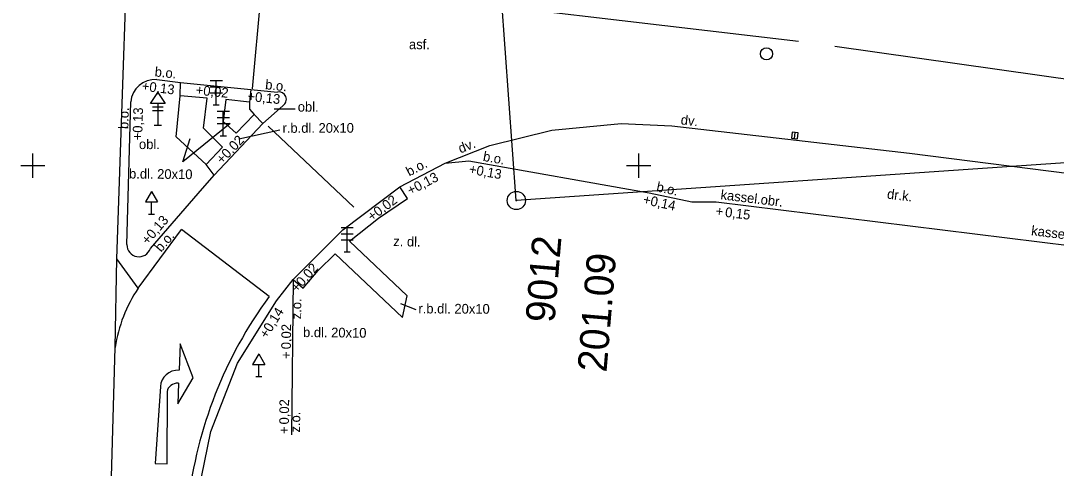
# Model space of a CAD drawing. Extents: x -598693 to -598240, y -1162454 to -1160800.
# Drawn here: x -598650.5 to -598607.77, y -1162412.48 to -1162394.03 of the extents above; entities that cross this region are included whole.
import ezdxf

# ---------------------------------------------------------------- set-up
doc = ezdxf.new("R2010")
doc.units = 0
for name, color, linetype in [('Vrstva 19', 7, 'Continuous'), ('Vrstva 2', 7, 'Continuous'), ('Vrstva 25', 7, 'Continuous'), ('Vrstva 44', 7, 'Continuous'), ('Vrstva 47', 7, 'Continuous'), ('Vrstva 49', 7, 'Continuous'), ('Vrstva 50', 7, 'Continuous'), ('Vrstva 61', 7, 'Continuous'), ('Vrstva 62', 7, 'Continuous'), ('Vrstva 7', 7, 'Continuous')]:
    doc.layers.add(name, color=color, linetype=linetype)

msp = doc.modelspace()

# ---------------------------------------------------------------- linework, layer by layer
at = {"layer": 'Vrstva 19'}
for p, q in [((-598642.18, -1162396.5), (-598642.68, -1162396.5)), ((-598642.43, -1162397.5), (-598642.43, -1162396.5)), ((-598642.68, -1162396.75), (-598642.18, -1162396.75)), ((-598642.68, -1162397), (-598642.18, -1162397)), ((-598642.555, -1162397.5), (-598642.305, -1162397.5)), ((-598641.89, -1162397.77), (-598642.39, -1162397.77)), ((-598642.14, -1162398.77), (-598642.14, -1162397.77)), ((-598642.39, -1162398.02), (-598641.89, -1162398.02)), ((-598642.39, -1162398.27), (-598641.89, -1162398.27)), ((-598642.265, -1162398.77), (-598642.015, -1162398.77)), ((-598645.1, -1162401.067), (-598645.35, -1162401.5)), ((-598645.1, -1162401.067), (-598644.85, -1162401.5)), ((-598645.35, -1162401.5), (-598644.85, -1162401.5)), ((-598645.1, -1162402), (-598645.1, -1162401.5)), ((-598645.225, -1162402), (-598644.975, -1162402)), ((-598636.78, -1162402.56), (-598637.28, -1162402.56)), ((-598637.03, -1162403.56), (-598637.03, -1162402.56)), ((-598637.28, -1162402.81), (-598636.78, -1162402.81)), ((-598637.28, -1162403.06), (-598636.78, -1162403.06)), ((-598637.155, -1162403.56), (-598636.905, -1162403.56)), ((-598640.68, -1162407.767), (-598640.93, -1162408.2)), ((-598640.68, -1162407.767), (-598640.43, -1162408.2)), ((-598640.93, -1162408.2), (-598640.43, -1162408.2)), ((-598640.68, -1162408.7), (-598640.68, -1162408.2)), ((-598640.805, -1162408.7), (-598640.555, -1162408.7))]:
    msp.add_line(p, q, dxfattribs=at)
at = {"layer": 'Vrstva 2'}
for radius in [0.375, 0.375, 0.0179, 0.0179]:
    msp.add_circle((-598630.05, -1162401.44), radius, dxfattribs=at)
at = {"layer": 'Vrstva 25'}
msp.add_line((-598618.574, -1162398.884), (-598618.546, -1162398.636), dxfattribs=at)
msp.add_lwpolyline([(-598618.449, -1162398.898), (-598618.422, -1162398.649), (-598618.671, -1162398.622), (-598618.698, -1162398.871)], close=True, dxfattribs=at)
msp.add_circle((-598619.73, -1162395.39), 0.25, dxfattribs=at)
at = {"layer": 'Vrstva 44'}
for p, q in [((-598644.846, -1162397.432), (-598644.846, -1162398.332)), ((-598645.066, -1162397.582), (-598644.618, -1162397.582)), ((-598645.066, -1162397.732), (-598644.623, -1162397.732)), ((-598644.996, -1162398.332), (-598644.696, -1162398.332))]:
    msp.add_line(p, q, dxfattribs=at)
msp.add_lwpolyline([(-598645.146, -1162397.437), (-598644.846, -1162396.982), (-598644.546, -1162397.437)], close=True, dxfattribs=at)
at = {"layer": 'Vrstva 47'}
for p, q in [((-598646.29, -1162396.66), (-598646.09, -1162390.77)), ((-598640.933, -1162396.84), (-598640.5, -1162392.12)), ((-598636.76, -1162401.72), (-598640.288, -1162398.368)), ((-598640.25, -1162405.4), (-598643.87, -1162402.63)), ((-598643.927, -1162407.343), (-598643.967, -1162408.437)), ((-598643.379, -1162408.757), (-598643.927, -1162407.343)), ((-598644.018, -1162409.829), (-598643.379, -1162408.757)), ((-598643.987, -1162408.974), (-598644.018, -1162409.829)), ((-598644.734, -1162409.106), (-598644.956, -1162412.285)), ((-598644.458, -1162412.303), (-598644.449, -1162409.315)), ((-598644.956, -1162412.285), (-598644.458, -1162412.303))]:
    msp.add_line(p, q, dxfattribs=at)
for points in [[(-598618.4, -1162394.88), (-598636.72, -1162392.72), (-598639.24, -1162392.43), (-598640.3, -1162392.34)], [(-598518.112, -1162407.899), (-598539.58, -1162405.31), (-598555.54, -1162403.37), (-598583.13, -1162399.87), (-598616.91, -1162395.09)], [(-598646.78, -1162413.81), (-598646.6, -1162407.5), (-598646.53, -1162403.85), (-598646.29, -1162396.66)], [(-598645.65, -1162405.05), (-598643.87, -1162402.63)], [(-598645.65, -1162405.05), (-598646.53, -1162403.85)]]:
    msp.add_lwpolyline(points, dxfattribs=at)
for centre, radius, start, end in [((-598640.778, -1162408.348), 5.883, 145.9018, 171.7101), ((-598625.961, -1162415.921), 17.744, 143.6356, 173.4606)]:
    msp.add_arc(centre, radius, start, end, dxfattribs=at)
for centre, major_axis, ratio in [((-598643.993, -1162409.133), (-0.742, 0.027), 0.937941), ((-598644.001, -1162409.332), (-0.449, 0.016), 0.797518)]:
    msp.add_ellipse(centre, major_axis=major_axis, ratio=ratio, start_param=4.712389, end_param=6.283185, dxfattribs=at)
at = {"layer": 'Vrstva 49'}
for p, q in [((-598640.04, -1162397.66), (-598639.18, -1162397.66)), ((-598641.86, -1162398.27), (-598643.816, -1162399.841)), ((-598641.5, -1162398.89), (-598639.81, -1162398.53)), ((-598643.816, -1162399.841), (-598643.51, -1162398.88)), ((-598634.83, -1162405.69), (-598634.19, -1162405.94))]:
    msp.add_line(p, q, dxfattribs=at)
at = {"layer": 'Vrstva 61'}
for p, q in [((-598630.05, -1162401.44), (-598634.92, -1162334.69)), ((-598547.54, -1162395.77), (-598630.05, -1162401.44))]:
    msp.add_line(p, q, dxfattribs=at)
at = {"layer": 'Vrstva 62'}
for p, q in [((-598650, -1162400.5), (-598650, -1162399.5)), ((-598625, -1162400.5), (-598625, -1162399.5)), ((-598650.5, -1162400), (-598649.5, -1162400)), ((-598625.5, -1162400), (-598624.5, -1162400))]:
    msp.add_line(p, q, dxfattribs=at)
at = {"layer": 'Vrstva 7'}
for points in [[(-598644.89, -1162396.45), (-598643.9, -1162396.57), (-598641.01, -1162396.86), (-598639.91, -1162396.97)], [(-598642.52, -1162400.39), (-598642.85, -1162399.96), (-598644.09, -1162398.82), (-598643.92, -1162397.12), (-598643.9, -1162396.57)], [(-598641.01, -1162396.86), (-598641.06, -1162397.38), (-598641.06, -1162397.67), (-598640.87, -1162397.9), (-598640.51, -1162398.27)], [(-598646.12, -1162403.26), (-598645.96, -1162397.37)], [(-598642.85, -1162399.96), (-598642.18, -1162399.24), (-598642.96, -1162398.46), (-598642.8, -1162397.22), (-598643.92, -1162397.12)], [(-598641.06, -1162397.38), (-598642.03, -1162397.28), (-598642.14, -1162398.18), (-598641.61, -1162398.66), (-598640.87, -1162397.9)], [(-598645.15, -1162403.42), (-598643.18, -1162401.15), (-598642.52, -1162400.39), (-598640.51, -1162398.27), (-598639.69, -1162397.53)], [(-598632.99, -1162399.9), (-598631.14, -1162399.17), (-598628.58, -1162398.54), (-598625.72, -1162398.27), (-598623.63, -1162398.36), (-598613.83, -1162399.49), (-598599.75, -1162401.27), (-598598.66, -1162402.55), (-598598.76, -1162402.66)], [(-598643.29, -1162414.06), (-598642.66, -1162410.96), (-598641.55, -1162408.14), (-598639.95, -1162405.58), (-598639.26, -1162404.7), (-598637.21, -1162402.65), (-598634.85, -1162400.87), (-598632.99, -1162399.9), (-598632.01, -1162399.8), (-598624.57, -1162401.12), (-598622.81, -1162401.5)], [(-598639.26, -1162404.7), (-598638.84, -1162405.05), (-598638.22, -1162404.32), (-598637.53, -1162403.64), (-598634.75, -1162406.26), (-598634.56, -1162405.37), (-598636.93, -1162403.12), (-598635.74, -1162402.17), (-598634.54, -1162401.35), (-598634.85, -1162400.87)], [(-598622.81, -1162401.5), (-598621.8, -1162401.5), (-598605.79, -1162403.47), (-598604.81, -1162403.68)], [(-598639.26, -1162404.7), (-598639.33, -1162411.1)]]:
    msp.add_lwpolyline(points, dxfattribs=at)
for centre, radius, start, end in [((-598644.954, -1162397.458), 1.01, 86.3595, 175.0193), ((-598639.842, -1162397.266), 0.304, 299.9028, 102.9927), ((-598645.622, -1162403.263), 0.498, 179.7084, 341.5585)]:
    msp.add_arc(centre, radius, start, end, dxfattribs=at)

# ---------------------------------------------------------------- texts
at = {"layer": 'Vrstva 2'}
for s, p in [(' 9012', (-598628.514, -1162406.949)), ('201.09 ', (-598626.33, -1162408.546))]:
    msp.add_text(s, height=1.2, rotation=85.2787, dxfattribs=at).set_placement(p)
at = {"layer": 'Vrstva 49'}
msp.add_text('asf.', height=0.4, dxfattribs=at).set_placement((-598634.48, -1162395.2))
for s, rotation, p in [('b.o.', 354.2894, (-598644.986, -1162396.32)), ('b.o.', 354.2894, (-598640.426, -1162396.85)), ('obl.', 359.7906, (-598639.069, -1162397.774)), ('b.o.', 88.444, (-598646.06, -1162398.497)), ('dv.', 353.4225, (-598623.281, -1162398.299)), ('r.b.dl. 20x10', 0.0923, (-598639.697, -1162398.649)), ('obl.', 359.6452, (-598645.621, -1162399.317)), ('dv.', 21.5339, (-598632.353, -1162399.502)), ('b.o.', 349.9393, (-598631.446, -1162399.804)), ('b.o.', 27.5423, (-598634.472, -1162400.455)), ('b.dl. 20x10', 359.3654, (-598646.031, -1162400.531)), ('b.o.', 347.8163, (-598624.294, -1162401.056)), ('kassel.obr.', 352.9851, (-598621.638, -1162401.386)), ('dr.k.', 352.9851, (-598614.768, -1162401.358)), ('kassel.obr.', 352.9851, (-598608.82, -1162402.866)), ('b.o.', 49.0472, (-598644.711, -1162403.592)), ('z. dl.', 358.6952, (-598635.131, -1162403.317)), ('z.o.', 89.3734, (-598638.93, -1162406.339)), ('r.b.dl. 20x10', 359.6483, (-598634.091, -1162406.092)), ('b.dl. 20x10', 359.3734, (-598638.852, -1162407.069)), ('z.o.', 89.3734, (-598638.973, -1162411.009))]:
    msp.add_text(s, height=0.4, rotation=rotation, dxfattribs=at).set_placement(p)
at = {"layer": 'Vrstva 50'}
for s, rotation, p in [('+0,13', 353.0888, (-598645.521, -1162396.906)), ('+0,02', 354.2698, (-598643.293, -1162397.072)), ('+0,13', 354.2894, (-598641.158, -1162397.33)), ('+0,13', 88.444, (-598645.488, -1162398.962)), ('+0,02', 46.5257, (-598642.184, -1162399.963)), ('+0,13', 349.9393, (-598632.028, -1162400.328)), ('+0,13', 27.5423, (-598634.423, -1162401.23)), ('+0,02', 37.025, (-598636.003, -1162402.313)), ('+0,14', 347.8163, (-598624.849, -1162401.574)), ('+', 352.9851, (-598621.843, -1162402.061)), ('0,15', 352.9851, (-598621.453, -1162402.109)), ('+0,13', 49.0472, (-598645.258, -1162403.292)), ('+0,02', 48.4667, (-598639.09, -1162405.255)), ('+0,14', 57.9946, (-598640.342, -1162407.16)), ('0,02', 89.3734, (-598639.351, -1162407.575)), ('+', 89.3734, (-598639.355, -1162407.969)), ('0,02', 89.3734, (-598639.433, -1162410.675)), ('+', 89.3734, (-598639.438, -1162411.068))]:
    msp.add_text(s, height=0.4, rotation=rotation, dxfattribs=at).set_placement(p)

doc.saveas('drawing.dxf')
